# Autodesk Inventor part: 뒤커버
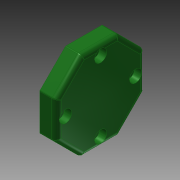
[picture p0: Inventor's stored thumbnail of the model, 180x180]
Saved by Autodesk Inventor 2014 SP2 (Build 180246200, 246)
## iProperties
Created: 2015-11
Part Number: 뒤커버
Material: 알루미늄 6061
Document SubType Name: Modeling
Designer: mduedu
Density: 1 g/cm^3
Appearance: 매끄러움 - 짙은 산림 녹색
Author: mduedu
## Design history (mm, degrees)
sketch "스케치5" dims "d66" = 58
  geometry: L1 (12.012, 29)-(29, 12.012); L2 (29, 12.012)-(29, -12.012); L3 (29, -12.012)-(12.012, -29); L4 (12.012, -29)-(-12.012, -29); L5 (-12.012, -29)-(-29, -12.012); L6 (-29, -12.012)-(-29, 12.012); L7 (-29, 12.012)-(-12.012, 29); L8 (-12.012, 29)-(12.012, 29); 4 further points
  constraints: 16 end point, 2 coincident, 2 vertical alignment, 1 midpoint, 19 other
extrude "돌출2" new body sketch "스케치5" distance "d67" = 11; taper "d68" = 0 deg
sketch "스케치6"
  geometry: C1 r 16 at (0, 0); 1 further point
  constraints: 1 centre point, 1 coincident
  dimensions: "d69" = 32 diameter of C1
extrude "돌출3" join sketch "스케치6" distance "d70" = 3; taper "d71" = 0 deg
hole "구멍5" diameter "d74" = 28; stored, may be unused: countersink angle "d78" = 90 deg, drill point angle "d80" = 0 deg; dims "d75" = 6, "d76" = 4, "d77" = 2, "d79" = 10, "d98" = 10, "d99" = 10
fillet "모깎기7" dims "d81" = 1
fillet "모깎기8" dims "d82" = 3
fillet "모깎기9" dims "d83" = 3
fillet "모깎기10" dims "d84" = 0.3
sketch "스케치7" dims "d85" = 46
  geometry: 3 further points
  constraints: 2 vertical alignment, 1 coincident, 2 other
hole "구멍6" sketch "스케치7" at (0, 23) diameter "d86" = 4.5; stored, may be unused: countersink angle "d90" = 90 deg, drill point angle "d92" = 0 deg; dims "d87" = 6, "d88" = 8, "d89" = 4.6, "d91" = 10
node "솔리드2"
pattern_circular "원형 패턴3" dims angle "d94" = 360 deg
